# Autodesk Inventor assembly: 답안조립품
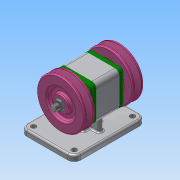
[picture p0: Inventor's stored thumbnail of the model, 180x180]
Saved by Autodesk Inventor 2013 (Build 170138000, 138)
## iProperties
Created: 2020-11
Part Number: 답안조립품
Document SubType Name: Assembly
Designer: Administrator
Author: Administrator
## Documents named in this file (10)
- C:\Users\Administrator\Desktop\701106V1018\답안조립품.iam
- C:\Users\Administrator\Desktop\701106V1018\본체.ipt
- C:\Users\Administrator\Desktop\701106V1018\베어링 6004.ipt
- C:\Users\Administrator\Desktop\701106V1018\오일 실 17 30 5.ipt
- C:\Users\Administrator\Desktop\701106V1018\커버.ipt
- C:\Users\Administrator\Desktop\701106V1018\축.ipt
- C:\Users\Administrator\Desktop\701106V1018\V-벨트풀리.ipt
- C:\Users\Administrator\Desktop\701106V1018\너트 M10x1.ipt
- C:\Users\Administrator\Desktop\701106V1018\키 5 x 5 x 12.ipt
- C:\Users\Administrator\Desktop\701106V1018\볼트 M4.ipt
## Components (2 placed, 1 different names)
1. V-벨트풀리:1 — 각도:4
2. V-벨트풀리:2 — 각도:2
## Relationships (2: Angle 2)
- 각도:2 [Angle]: V-벨트풀리:2
- 각도:4 [Angle]: V-벨트풀리:1
